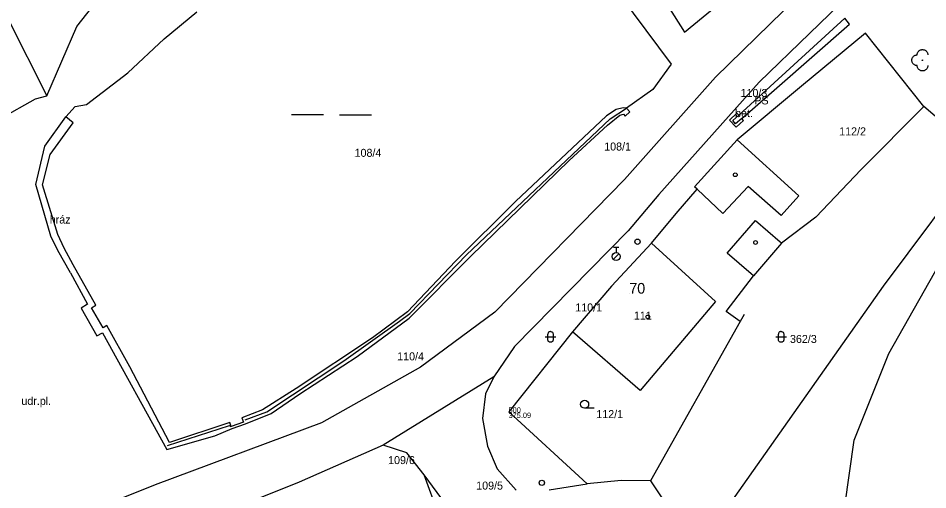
# Model space of a CAD drawing. Extents: x -836739 to -835945, y -1070775 to -1070126.
# Drawn here: x -836543.2 to -836458, y -1070319.5 to -1070275.3 of the extents above; entities that cross this region are included whole.
import ezdxf

# ---------------------------------------------------------------- set-up
doc = ezdxf.new("R2010")
doc.units = 0
for name, color, linetype in [('BodPole_mer', 7, 'Continuous'), ('BodPole_popis', 7, 'Continuous'), ('Budovy_hranice', 7, 'Continuous'), ('Budovy_kody', 7, 'Continuous'), ('Doprava_hranice', 7, 'Continuous'), ('OstPloch_hranice', 7, 'Continuous'), ('OstPloch_kody', 7, 'Continuous'), ('PovrZnIS_body', 7, 'Continuous'), ('RuianAdr_popis', 7, 'Continuous'), ('RuianPar_popis', 7, 'Continuous'), ('Stavby_hr_stav', 7, 'Continuous'), ('Stavby_kody', 7, 'Continuous'), ('Stavby_linie', 7, 'Continuous'), ('Vodstvo_hranice', 7, 'Continuous'), ('Vodstvo_kody', 7, 'Continuous'), ('Zelen_body', 7, 'Continuous'), ('Zelen_kody', 7, 'Continuous')]:
    doc.layers.add(name, color=color, linetype=linetype)

msp = doc.modelspace()

# ---------------------------------------------------------------- linework, layer by layer
at = {"layer": 'BodPole_mer'}
for p, q in [((-836537.68, -1070276.1), (-836537.68, -1070276.1)), ((-836465.76, -1070275.33), (-836465.76, -1070275.33)), ((-836465.3, -1070275.87), (-836465.3, -1070275.87)), ((-836480.77, -1070276.62), (-836480.77, -1070276.62)), ((-836463.82, -1070276.71), (-836463.82, -1070276.71)), ((-836529.5, -1070277.24), (-836529.5, -1070277.24)), ((-836458.48, -1070279.26), (-836458.48, -1070279.26)), ((-836482.01, -1070279.63), (-836482.01, -1070279.63)), ((-836532.91, -1070280.44), (-836532.91, -1070280.44)), ((-836477.85, -1070280.85), (-836477.85, -1070280.85)), ((-836483.74, -1070282.01), (-836483.74, -1070282.01)), ((-836473.79, -1070281.33), (-836473.79, -1070281.33)), ((-836469.8, -1070281.7), (-836469.8, -1070281.7)), ((-836541.56, -1070282.89), (-836541.56, -1070282.89)), ((-836540.5, -1070282.59), (-836540.5, -1070282.59)), ((-836537.84, -1070283.58), (-836537.84, -1070283.58)), ((-836536.78, -1070283.42), (-836536.78, -1070283.42)), ((-836486.51, -1070283.72), (-836486.51, -1070283.72)), ((-836486.21, -1070283.75), (-836486.21, -1070283.75)), ((-836458.36, -1070283.6), (-836458.36, -1070283.6)), ((-836538.7, -1070284.57), (-836538.7, -1070284.57)), ((-836488.08, -1070284.48), (-836488.08, -1070284.48)), ((-836487.17, -1070283.89), (-836487.17, -1070283.89)), ((-836486.83, -1070284.4), (-836486.83, -1070284.4)), ((-836486.48, -1070284.32), (-836486.48, -1070284.32)), ((-836486.34, -1070284.49), (-836486.34, -1070284.49)), ((-836485.89, -1070284.09), (-836485.89, -1070284.09)), ((-836475.86, -1070284.22), (-836475.86, -1070284.22)), ((-836475.69, -1070284.41), (-836475.69, -1070284.41)), ((-836538.02, -1070285.12), (-836538.02, -1070285.12)), ((-836487.98, -1070285.34), (-836487.98, -1070285.34)), ((-836487.74, -1070284.74), (-836487.74, -1070284.74)), ((-836476.56, -1070284.86), (-836476.56, -1070284.86)), ((-836476.25, -1070284.92), (-836476.25, -1070284.92)), ((-836475.98, -1070285.22), (-836475.98, -1070285.22)), ((-836475.41, -1070284.71), (-836475.41, -1070284.71)), ((-836475.24, -1070284.9), (-836475.24, -1070284.9)), ((-836475.94, -1070285.54), (-836475.94, -1070285.54)), ((-836475.84, -1070286.72), (-836475.84, -1070286.72)), ((-836540.69, -1070287.31), (-836540.69, -1070287.31)), ((-836540.19, -1070288.1), (-836540.19, -1070288.1)), ((-836491.56, -1070288.65), (-836491.56, -1070288.65)), ((-836464.21, -1070289.51), (-836464.21, -1070289.51)), ((-836486.39, -1070290.44), (-836486.39, -1070290.44)), ((-836541.54, -1070290.91), (-836541.54, -1070290.91)), ((-836540.9, -1070290.92), (-836540.9, -1070290.92)), ((-836479.82, -1070291.11), (-836479.82, -1070291.11)), ((-836479.59, -1070291.33), (-836479.59, -1070291.33)), ((-836474.82, -1070291.1), (-836474.82, -1070291.1)), ((-836483.18, -1070291.85), (-836483.18, -1070291.85)), ((-836470.06, -1070291.96), (-836470.06, -1070291.96)), ((-836496.59, -1070292.51), (-836496.59, -1070292.51)), ((-836481.56, -1070293.61), (-836481.56, -1070293.61)), ((-836477.18, -1070293.62), (-836477.18, -1070293.62)), ((-836471.71, -1070293.81), (-836471.71, -1070293.81)), ((-836468.46, -1070293.96), (-836468.46, -1070293.96)), ((-836474.12, -1070294.28), (-836474.12, -1070294.28)), ((-836539.46, -1070295.59), (-836539.46, -1070295.59)), ((-836486.04, -1070295.25), (-836486.04, -1070295.25)), ((-836540.11, -1070295.73), (-836540.11, -1070295.73)), ((-836485.17, -1070296.27), (-836485.17, -1070296.27)), ((-836483.87, -1070296.4), (-836483.87, -1070296.4)), ((-836471.8, -1070296.28), (-836471.8, -1070296.28)), ((-836471.67, -1070296.39), (-836471.67, -1070296.39)), ((-836539.47, -1070297.1), (-836539.47, -1070297.1)), ((-836538.87, -1070296.86), (-836538.87, -1070296.86)), ((-836476.76, -1070297.35), (-836476.76, -1070297.35)), ((-836502.23, -1070298.08), (-836502.23, -1070298.08)), ((-836501.2, -1070297.48), (-836501.2, -1070297.48)), ((-836500.78, -1070297.61), (-836500.78, -1070297.61)), ((-836487.17, -1070297.65), (-836487.17, -1070297.65)), ((-836538.03, -1070298.42), (-836538.03, -1070298.42)), ((-836538.28, -1070299.17), (-836538.28, -1070299.17)), ((-836474.52, -1070299.27), (-836474.52, -1070299.27)), ((-836474.31, -1070299.45), (-836474.31, -1070299.45)), ((-836487.6, -1070300.42), (-836487.6, -1070300.42)), ((-836462.13, -1070300.43), (-836462.13, -1070300.43)), ((-836537.27, -1070302.49), (-836537.27, -1070302.49)), ((-836536.67, -1070302.12), (-836536.67, -1070302.12)), ((-836536.32, -1070302.47), (-836536.32, -1070302.47)), ((-836535.91, -1070302.21), (-836535.91, -1070302.21)), ((-836477.87, -1070301.86), (-836477.87, -1070301.86)), ((-836506.71, -1070302.82), (-836506.71, -1070302.82)), ((-836506.51, -1070302.98), (-836506.51, -1070302.98)), ((-836498.54, -1070302.85), (-836498.54, -1070302.85)), ((-836476.86, -1070302.79), (-836476.86, -1070302.79)), ((-836475.18, -1070303.07), (-836475.18, -1070303.07)), ((-836534.86, -1070304.13), (-836534.86, -1070304.13)), ((-836507.45, -1070303.71), (-836507.45, -1070303.71)), ((-836506.56, -1070303.42), (-836506.56, -1070303.42)), ((-836475.56, -1070303.74), (-836475.56, -1070303.74)), ((-836535.82, -1070305.08), (-836535.82, -1070305.08)), ((-836535.28, -1070304.8), (-836535.28, -1070304.8)), ((-836535.22, -1070304.34), (-836535.22, -1070304.34)), ((-836491.27, -1070304.7), (-836491.27, -1070304.7)), ((-836509.99, -1070305.26), (-836509.99, -1070305.26)), ((-836496.69, -1070306.07), (-836496.69, -1070306.07)), ((-836461.62, -1070306.74), (-836461.62, -1070306.74)), ((-836512.67, -1070307.44), (-836512.67, -1070307.44)), ((-836511.44, -1070307.01), (-836511.44, -1070307.01)), ((-836532.73, -1070307.98), (-836532.73, -1070307.98)), ((-836505.49, -1070308.01), (-836505.49, -1070308.01)), ((-836498.64, -1070308.92), (-836498.64, -1070308.92)), ((-836517.14, -1070310.02), (-836517.14, -1070310.02)), ((-836516.81, -1070310.51), (-836516.81, -1070310.51)), ((-836499.4, -1070310.53), (-836499.4, -1070310.53)), ((-836484.93, -1070310.21), (-836484.93, -1070310.21)), ((-836522.22, -1070312.76), (-836522.22, -1070312.76)), ((-836520.29, -1070312.03), (-836520.29, -1070312.03)), ((-836519.9, -1070312.2), (-836519.9, -1070312.2)), ((-836519.48, -1070312.36), (-836519.48, -1070312.36)), ((-836497.25, -1070312.28), (-836497.25, -1070312.28)), ((-836497.22, -1070312.21), (-836497.22, -1070312.21)), ((-836523.38, -1070313.48), (-836523.38, -1070313.48)), ((-836523.35, -1070313.2), (-836523.35, -1070313.2)), ((-836523.23, -1070313.58), (-836523.23, -1070313.58)), ((-836522.07, -1070313.16), (-836522.07, -1070313.16)), ((-836521.92, -1070312.95), (-836521.92, -1070312.95)), ((-836521.89, -1070313.32), (-836521.89, -1070313.32)), ((-836514.78, -1070313.23), (-836514.78, -1070313.23)), ((-836499.69, -1070312.83), (-836499.69, -1070312.83)), ((-836524.75, -1070314.46), (-836524.75, -1070314.46)), ((-836523.12, -1070313.78), (-836523.12, -1070313.78)), ((-836529.02, -1070315.07), (-836529.02, -1070315.07)), ((-836464.89, -1070314.87), (-836464.89, -1070314.87)), ((-836529.27, -1070315.73), (-836529.27, -1070315.73)), ((-836529.2, -1070315.35), (-836529.2, -1070315.35)), ((-836508.98, -1070315.34), (-836508.98, -1070315.34)), ((-836506.77, -1070316.06), (-836506.77, -1070316.06)), ((-836499.23, -1070315.41), (-836499.23, -1070315.41)), ((-836498.31, -1070317.53), (-836498.31, -1070317.53)), ((-836505.15, -1070318.12), (-836505.15, -1070318.12)), ((-836486.71, -1070318.63), (-836486.71, -1070318.63)), ((-836483.95, -1070318.68), (-836483.95, -1070318.68)), ((-836530.36, -1070319.04), (-836530.36, -1070319.04)), ((-836516.87, -1070318.79), (-836516.87, -1070318.79)), ((-836494.13, -1070318.86), (-836494.13, -1070318.86)), ((-836489.89, -1070318.94), (-836489.89, -1070318.94))]:
    msp.add_line(p, q, dxfattribs=at)
at = {"layer": 'Budovy_hranice'}
for p, q in [((-836475.84, -1070286.72), (-836479.82, -1070291.11)), ((-836487.6, -1070300.42), (-836491.27, -1070304.7))]:
    msp.add_line(p, q, dxfattribs=at)
for points in [[(-836475.84, -1070286.72), (-836470.06, -1070291.96), (-836471.71, -1070293.81), (-836474.82, -1070291.1), (-836477.18, -1070293.62), (-836479.59, -1070291.33), (-836479.82, -1070291.11)], [(-836474.31, -1070299.45), (-836474.52, -1070299.27), (-836476.76, -1070297.35), (-836474.12, -1070294.28), (-836471.8, -1070296.28), (-836471.67, -1070296.39), (-836474.31, -1070299.45)], [(-836487.6, -1070300.42), (-836483.87, -1070296.4), (-836477.87, -1070301.86), (-836484.93, -1070310.21), (-836491.27, -1070304.7)]]:
    msp.add_lwpolyline(points, dxfattribs=at)
at = {"layer": 'Budovy_kody'}
for centre in [(-836476.01, -1070289.99), (-836474.11, -1070296.34), (-836484.2, -1070303.31)]:
    msp.add_circle(centre, 0.175, dxfattribs=at)
at = {"layer": 'Doprava_hranice'}
for points in [[(-836463.13, -1070260.78), (-836461.66, -1070261.68), (-836460.5, -1070262.24), (-836459.09, -1070262.17), (-836456.22, -1070259.67), (-836453.89, -1070261.93), (-836464.34, -1070272.16), (-836473.79, -1070281.33)], [(-836463.13, -1070260.78), (-836466.54, -1070263.19), (-836466.2, -1070265.91), (-836466.63, -1070266.39), (-836466.02, -1070267.34), (-836466.37, -1070268.96), (-836467.68, -1070270.88), (-836477.85, -1070280.85), (-836486.39, -1070290.44)], [(-836473.79, -1070281.33), (-836483.18, -1070291.85), (-836486.04, -1070295.25), (-836496.69, -1070306.07), (-836498.64, -1070308.92), (-836508.98, -1070315.34), (-836516.87, -1070318.79), (-836525.05, -1070322.08), (-836528.75, -1070323.23)], [(-836486.39, -1070290.44), (-836498.54, -1070302.85), (-836505.49, -1070308.01), (-836514.78, -1070313.23), (-836530.36, -1070319.04), (-836537.03, -1070321.73), (-836555.38, -1070326.29), (-836561.14, -1070327.96), (-836562.04, -1070328.06)], [(-836498.64, -1070308.92), (-836499.4, -1070310.53), (-836499.69, -1070312.83), (-836499.23, -1070315.41), (-836498.31, -1070317.53), (-836496.52, -1070319.54)], [(-836536.4, -1070368.21), (-836533.17, -1070355.68), (-836529.95, -1070350.14), (-836526.64, -1070346.09), (-836522.06, -1070342.08), (-836518.27, -1070339.72), (-836511.7, -1070337.08), (-836507.28, -1070334.68), (-836504.64, -1070331.81), (-836503.25, -1070329.28), (-836502.09, -1070325.77), (-836501.89, -1070323.62), (-836502.72, -1070321.42), (-836505.15, -1070318.12), (-836506.77, -1070316.06), (-836508.98, -1070315.34)], [(-836541.58, -1070350.39), (-836544.34, -1070349.63), (-836547.79, -1070346.93), (-836549.07, -1070344.38), (-836548.75, -1070338.43), (-836546.32, -1070335.63), (-836537.04, -1070331.76), (-836528.76, -1070329.97), (-836518.57, -1070326.72), (-836515.72, -1070324.62), (-836506.05, -1070328.35), (-836503.77, -1070324.55), (-836503.82, -1070321.79), (-836505.15, -1070318.12)]]:
    msp.add_lwpolyline(points, dxfattribs=at)
at = {"layer": 'OstPloch_hranice'}
for p, q in [((-836523.38, -1070313.48), (-836523.23, -1070313.58)), ((-836493.44, -1070319.52), (-836489.89, -1070318.94))]:
    msp.add_line(p, q, dxfattribs=at)
for points in [[(-836549.52, -1070233.43), (-836549.19, -1070238.84), (-836548.54, -1070250.58), (-836549.98, -1070264.67), (-836547.91, -1070263.48), (-836544.14, -1070275.36), (-836540.5, -1070282.59), (-836537.68, -1070276.1), (-836535.35, -1070273.1), (-836529.71, -1070265.69)], [(-836356.62, -1070406.87), (-836370.19, -1070399.44), (-836385.43, -1070392.2), (-836396.38, -1070386.03), (-836404.41, -1070381.11), (-836409.87, -1070376.61), (-836425.28, -1070363.93), (-836449.03, -1070345.44), (-836455, -1070340), (-836462.64, -1070329.11), (-836464.81, -1070325.47), (-836465.74, -1070321.03), (-836464.89, -1070314.87), (-836461.62, -1070306.74), (-836456.41, -1070297.54), (-836450.95, -1070288.2), (-836447.03, -1070272.79), (-836441.38, -1070260.76)], [(-836544.78, -1070284.68), (-836541.56, -1070282.89), (-836540.5, -1070282.59)]]:
    msp.add_lwpolyline(points, dxfattribs=at)
at = {"layer": 'OstPloch_kody'}
for p, q in [((-836493.57, -1070305.43), (-836493.57, -1070304.93)), ((-836493.07, -1070304.93), (-836493.07, -1070305.43)), ((-836471.97, -1070305.43), (-836471.97, -1070304.93)), ((-836471.47, -1070304.93), (-836471.47, -1070305.43)), ((-836493.82, -1070305.18), (-836492.82, -1070305.18)), ((-836472.22, -1070305.18), (-836471.22, -1070305.18)), ((-836489.245, -1070311.87), (-836490.12, -1070311.87))]:
    msp.add_line(p, q, dxfattribs=at)
for points in [[(-836493.32, -1070304.68), (-836493.365, -1070304.684), (-836493.412, -1070304.698), (-836493.457, -1070304.721), (-836493.497, -1070304.753), (-836493.529, -1070304.793), (-836493.552, -1070304.838), (-836493.566, -1070304.885), (-836493.57, -1070304.93)], [(-836493.32, -1070304.68), (-836493.275, -1070304.684), (-836493.228, -1070304.698), (-836493.183, -1070304.721), (-836493.143, -1070304.753), (-836493.111, -1070304.793), (-836493.088, -1070304.838), (-836493.074, -1070304.885), (-836493.07, -1070304.93)], [(-836471.72, -1070304.68), (-836471.765, -1070304.684), (-836471.812, -1070304.698), (-836471.857, -1070304.721), (-836471.897, -1070304.753), (-836471.929, -1070304.793), (-836471.952, -1070304.838), (-836471.966, -1070304.885), (-836471.97, -1070304.93)], [(-836471.72, -1070304.68), (-836471.675, -1070304.684), (-836471.628, -1070304.698), (-836471.583, -1070304.721), (-836471.543, -1070304.753), (-836471.511, -1070304.793), (-836471.488, -1070304.838), (-836471.474, -1070304.885), (-836471.47, -1070304.93)], [(-836493.32, -1070305.68), (-836493.365, -1070305.676), (-836493.412, -1070305.662), (-836493.457, -1070305.639), (-836493.497, -1070305.607), (-836493.529, -1070305.567), (-836493.552, -1070305.522), (-836493.566, -1070305.475), (-836493.57, -1070305.43)], [(-836493.07, -1070305.43), (-836493.074, -1070305.475), (-836493.088, -1070305.522), (-836493.111, -1070305.567), (-836493.143, -1070305.607), (-836493.183, -1070305.639), (-836493.228, -1070305.662), (-836493.275, -1070305.676), (-836493.32, -1070305.68)], [(-836471.72, -1070305.68), (-836471.765, -1070305.676), (-836471.812, -1070305.662), (-836471.857, -1070305.639), (-836471.897, -1070305.607), (-836471.929, -1070305.567), (-836471.952, -1070305.522), (-836471.966, -1070305.475), (-836471.97, -1070305.43)], [(-836471.47, -1070305.43), (-836471.474, -1070305.475), (-836471.488, -1070305.522), (-836471.511, -1070305.567), (-836471.543, -1070305.607), (-836471.583, -1070305.639), (-836471.628, -1070305.662), (-836471.675, -1070305.676), (-836471.72, -1070305.68)]]:
    msp.add_lwpolyline(points, dxfattribs=at)
msp.add_ellipse((-836490.12, -1070311.495), major_axis=(0.375, 0), ratio=0.999999, dxfattribs=at)
at = {"layer": 'PovrZnIS_body'}
for p, q in [((-836486.905, -1070297.385), (-836487.435, -1070297.915)), ((-836487.42, -1070296.775), (-836486.92, -1070296.775)), ((-836487.17, -1070296.775), (-836487.17, -1070297.275))]:
    msp.add_line(p, q, dxfattribs=at)
for centre, radius in [((-836485.17, -1070296.27), 0.25), ((-836487.17, -1070297.65), 0.375), ((-836494.13, -1070318.86), 0.25)]:
    msp.add_circle(centre, radius, dxfattribs=at)
at = {"layer": 'RuianAdr_popis'}
msp.add_line((-836485.94, -1070301.13), (-836485.94, -1070301.13), dxfattribs=at)
at = {"layer": 'RuianPar_popis'}
for p, q in [((-836475.52, -1070282.7), (-836475.52, -1070282.7)), ((-836466.28, -1070286.3), (-836466.28, -1070286.3)), ((-836488.29, -1070287.72), (-836488.29, -1070287.72)), ((-836511.67, -1070288.31), (-836511.67, -1070288.31)), ((-836491, -1070302.8), (-836491, -1070302.8)), ((-836485.51, -1070303.56), (-836485.51, -1070303.56)), ((-836470.89, -1070305.75), (-836470.89, -1070305.75)), ((-836507.68, -1070307.38), (-836507.68, -1070307.38)), ((-836489.03, -1070312.79), (-836489.03, -1070312.79)), ((-836508.53, -1070317.1), (-836508.53, -1070317.1)), ((-836500.28, -1070319.49), (-836500.28, -1070319.49))]:
    msp.add_line(p, q, dxfattribs=at)
at = {"layer": 'Stavby_hr_stav'}
for points in [[(-836475.41, -1070284.71), (-836465.3, -1070275.87), (-836465.76, -1070275.33), (-836475.69, -1070284.41)], [(-836475.86, -1070284.22), (-836476.56, -1070284.86), (-836475.94, -1070285.54), (-836475.24, -1070284.9), (-836475.41, -1070284.71), (-836475.98, -1070285.22), (-836476.25, -1070284.92), (-836475.69, -1070284.41), (-836475.86, -1070284.22)]]:
    msp.add_lwpolyline(points, dxfattribs=at)
at = {"layer": 'Stavby_linie'}
for p, q in [((-836463.82, -1070276.71), (-836469.8, -1070281.7)), ((-836458.36, -1070283.6), (-836463.82, -1070276.71)), ((-836469.8, -1070281.7), (-836475.84, -1070286.72)), ((-836481.56, -1070293.61), (-836479.59, -1070291.33)), ((-836483.87, -1070296.4), (-836481.56, -1070293.61)), ((-836476.86, -1070302.79), (-836474.31, -1070299.45)), ((-836475.56, -1070303.74), (-836476.86, -1070302.79)), ((-836529.2, -1070315.35), (-836523.38, -1070313.48))]:
    msp.add_line(p, q, dxfattribs=at)
for points in [[(-836490.71, -1070260.96), (-836485.67, -1070268.85), (-836480.77, -1070276.62), (-836476.92, -1070273.45)], [(-836521.92, -1070312.95), (-836519.9, -1070312.2), (-836512.67, -1070307.44), (-836507.45, -1070303.71), (-836506.51, -1070302.98), (-836501.2, -1070297.48), (-836487.74, -1070284.74), (-836486.21, -1070283.75)], [(-836483.95, -1070318.68), (-836480.18, -1070324.33), (-836477.38, -1070322.05), (-836462.13, -1070300.43), (-836452.98, -1070288.18), (-836458.36, -1070283.6)], [(-836458.36, -1070283.6), (-836464.21, -1070289.51), (-836468.46, -1070293.96), (-836471.67, -1070296.39)], [(-836475.18, -1070303.07), (-836475.56, -1070303.74), (-836483.95, -1070318.68)], [(-836491.27, -1070304.7), (-836497.22, -1070312.21), (-836489.89, -1070318.94)], [(-836483.95, -1070318.68), (-836486.71, -1070318.63), (-836489.89, -1070318.94)]]:
    msp.add_lwpolyline(points, dxfattribs=at)
at = {"layer": 'Vodstvo_hranice'}
for points in [[(-836486.76, -1070273.24), (-836482.01, -1070279.63), (-836483.74, -1070282.01), (-836486.21, -1070283.75)], [(-836486.21, -1070283.75), (-836486.51, -1070283.72), (-836487.17, -1070283.89), (-836488.08, -1070284.48), (-836496.59, -1070292.51), (-836502.23, -1070298.08), (-836506.71, -1070302.82), (-836509.99, -1070305.26), (-836517.14, -1070310.02), (-836520.29, -1070312.03), (-836522.22, -1070312.76), (-836522.07, -1070313.16), (-836523.23, -1070313.58), (-836523.35, -1070313.2), (-836529.02, -1070315.07), (-836532.73, -1070307.98), (-836534.86, -1070304.13), (-836535.22, -1070304.34), (-836536.32, -1070302.47), (-836535.91, -1070302.21), (-836538.03, -1070298.42), (-836538.87, -1070296.86), (-836539.46, -1070295.59), (-836540.9, -1070290.92), (-836540.19, -1070288.1), (-836538.02, -1070285.12), (-836538.7, -1070284.57), (-836537.84, -1070283.58), (-836536.78, -1070283.42), (-836532.91, -1070280.44), (-836529.5, -1070277.24), (-836526.44, -1070274.72)], [(-836538.28, -1070299.17), (-836536.67, -1070302.12), (-836537.27, -1070302.49), (-836535.82, -1070305.08), (-836535.28, -1070304.8), (-836529.27, -1070315.73), (-836524.75, -1070314.46), (-836523.12, -1070313.78), (-836521.89, -1070313.32), (-836519.48, -1070312.36), (-836516.81, -1070310.51), (-836511.44, -1070307.01), (-836506.56, -1070303.42), (-836500.78, -1070297.61), (-836491.56, -1070288.65), (-836487.98, -1070285.34), (-836486.83, -1070284.4), (-836486.48, -1070284.32), (-836486.34, -1070284.49), (-836485.89, -1070284.09), (-836486.21, -1070283.75)], [(-836538.28, -1070299.17), (-836539.47, -1070297.1), (-836540.11, -1070295.73), (-836541.54, -1070290.91), (-836540.69, -1070287.31), (-836538.7, -1070284.57)]]:
    msp.add_lwpolyline(points, dxfattribs=at)
at = {"layer": 'Vodstvo_kody'}
for p, q in [((-836514.57, -1070284.39), (-836517.57, -1070284.39)), ((-836513.07, -1070284.39), (-836510.07, -1070284.39))]:
    msp.add_line(p, q, dxfattribs=at)
at = {"layer": 'Zelen_body'}
msp.add_line((-836458.48, -1070279.26), (-836458.48, -1070279.26), dxfattribs=at)
for points in [[(-836458.98, -1070278.76), (-836458.978, -1070278.712), (-836458.97, -1070278.663), (-836458.958, -1070278.613), (-836458.94, -1070278.564), (-836458.916, -1070278.515), (-836458.887, -1070278.469), (-836458.853, -1070278.426), (-836458.814, -1070278.387), (-836458.771, -1070278.353), (-836458.725, -1070278.324), (-836458.676, -1070278.3), (-836458.627, -1070278.282), (-836458.577, -1070278.27), (-836458.528, -1070278.262), (-836458.48, -1070278.26), (-836458.432, -1070278.262), (-836458.383, -1070278.27), (-836458.333, -1070278.282), (-836458.284, -1070278.3), (-836458.235, -1070278.324), (-836458.189, -1070278.353), (-836458.146, -1070278.387), (-836458.107, -1070278.426), (-836458.073, -1070278.469), (-836458.044, -1070278.515), (-836458.02, -1070278.564), (-836458.002, -1070278.613), (-836457.99, -1070278.663), (-836457.982, -1070278.712), (-836457.98, -1070278.76)], [(-836458.98, -1070279.76), (-836459.028, -1070279.758), (-836459.077, -1070279.75), (-836459.127, -1070279.738), (-836459.176, -1070279.72), (-836459.225, -1070279.696), (-836459.271, -1070279.667), (-836459.314, -1070279.633), (-836459.353, -1070279.594), (-836459.387, -1070279.551), (-836459.416, -1070279.505), (-836459.44, -1070279.456), (-836459.458, -1070279.407), (-836459.47, -1070279.357), (-836459.478, -1070279.308), (-836459.48, -1070279.26), (-836459.478, -1070279.212), (-836459.47, -1070279.163), (-836459.458, -1070279.113), (-836459.44, -1070279.064), (-836459.416, -1070279.015), (-836459.387, -1070278.969), (-836459.353, -1070278.926), (-836459.314, -1070278.887), (-836459.271, -1070278.853), (-836459.225, -1070278.824), (-836459.176, -1070278.8), (-836459.127, -1070278.782), (-836459.077, -1070278.77), (-836459.028, -1070278.762), (-836458.98, -1070278.76)], [(-836457.98, -1070279.76), (-836457.982, -1070279.808), (-836457.99, -1070279.857), (-836458.002, -1070279.907), (-836458.02, -1070279.956), (-836458.044, -1070280.005), (-836458.073, -1070280.051), (-836458.107, -1070280.094), (-836458.146, -1070280.133), (-836458.189, -1070280.167), (-836458.235, -1070280.196), (-836458.284, -1070280.22), (-836458.333, -1070280.238), (-836458.383, -1070280.25), (-836458.432, -1070280.258), (-836458.48, -1070280.26), (-836458.528, -1070280.258), (-836458.577, -1070280.25), (-836458.627, -1070280.238), (-836458.676, -1070280.22), (-836458.725, -1070280.196), (-836458.771, -1070280.167), (-836458.814, -1070280.133), (-836458.853, -1070280.094), (-836458.887, -1070280.051), (-836458.916, -1070280.005), (-836458.94, -1070279.956), (-836458.958, -1070279.907), (-836458.97, -1070279.857), (-836458.978, -1070279.808), (-836458.98, -1070279.76)]]:
    msp.add_lwpolyline(points, dxfattribs=at)
msp.add_ellipse((-836458.48, -1070279.26), major_axis=(0.025, 0), ratio=0.999997, dxfattribs=at)

# ---------------------------------------------------------------- texts
at = {"layer": 'BodPole_popis'}
for s, p in [('500', (-836497.25, -1070312.28)), ('375.09', (-836497.25, -1070312.78))]:
    msp.add_text(s, height=0.5, dxfattribs=at).set_placement(p)
at = {"layer": 'RuianAdr_popis'}
msp.add_text('70', height=1, dxfattribs=at).set_placement((-836485.94, -1070301.13))
at = {"layer": 'RuianPar_popis'}
for s, p in [('110/3', (-836475.52, -1070282.7)), ('112/2', (-836466.28, -1070286.3)), ('108/1', (-836488.29, -1070287.72)), ('108/4', (-836511.67, -1070288.31)), ('110/1', (-836491, -1070302.8)), ('111', (-836485.51, -1070303.56)), ('362/3', (-836470.89, -1070305.75)), ('110/4', (-836507.68, -1070307.38)), ('112/1', (-836489.03, -1070312.79)), ('109/6', (-836508.53, -1070317.1)), ('109/5', (-836500.28, -1070319.49))]:
    msp.add_text(s, height=0.75, dxfattribs=at).set_placement(p)
at = {"layer": 'Stavby_kody'}
for s, p in [('PS', (-836474.23, -1070283.4)), ('bet.', (-836476.03, -1070284.59))]:
    msp.add_text(s, height=0.75, dxfattribs=at).set_placement(p)
at = {"layer": 'Vodstvo_kody'}
msp.add_text('hráz', height=0.75, dxfattribs=at).set_placement((-836540.22, -1070294.56))
at = {"layer": 'Zelen_kody'}
msp.add_text('udr.pl.', height=0.75, dxfattribs=at).set_placement((-836542.88, -1070311.56))

doc.saveas('drawing.dxf')
